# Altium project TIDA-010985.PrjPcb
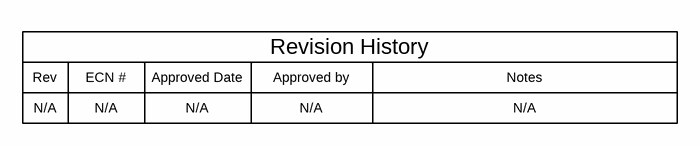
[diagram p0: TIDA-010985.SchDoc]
TID: N/A; TechSupport: http://www.ti.com/support; SCH_Rev: E2; PRJ_Title: Insulation Monitor; PRJ_Number: TIDA-010985; PRJ_Engineer: Kelvin Le; PRJ_Customer: Public Release; PCB_Rev: E2; PCB_Layout: Kelvin Le; CopyrightYear: 2025
5 sheets, 150 parts. Net scope: global (net labels, ports and power ports of the same name join across sheets).
Board file: TIDA-010985.PcbDoc
Sheets:
  TIDA-010985.SchDoc
  TIDA-010985_AFE.SchDoc
  TIDA-010985_Hardware.SchDoc
  TIDA-010985_Connectors_Aux_PWR.SchDoc
  TIDA-010985_CAN.SchDoc

## Sheet TIDA-010985.SchDoc
size 431 x 279 mm; Date: Not shown in title block; ApprovedBy: Not shown in title block; CheckedBy: Not shown in title block; Author: Not shown in title block; CompanyName: Not shown in title block; Engineer: Not shown in title block; Organization: Not shown in title block; Address1: Not shown in title block; Address2: Not shown in title block; Address3: Not shown in title block; Address4: Not shown in title block; DocumentNumber: 1; Revision: Use project parameter SCH_Rev; SheetNumber: 1; SheetTotal: 5; PageSetup: Record=PageOptions¦CenterHorizontal=True¦CenterVertical=True¦PrintScale=1.00¦XCorrection=1.00¦YCorrection=1.00¦PrintKind=0¦BorderSize=5000000¦LeftOffset=0¦BottomOffset=0¦Orientation=2¦PaperLength=1000¦PaperWidth=1000¦Scale=100¦PaperSource=15¦PrintQuality=600¦MediaType=1¦DitherType=10¦PaperKind=Letter¦PrintScaleMode=1

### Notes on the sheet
- Rev
- N/A
- ECN #
- Approved Date
- Approved by
- Revision History
- Notes

## Sheet TIDA-010985_AFE.SchDoc
size 431 x 279 mm; Date: Not shown in title block; ApprovedBy: Not shown in title block; CheckedBy: Not shown in title block; Author: Not shown in title block; CompanyName: Not shown in title block; Engineer: Not shown in title block; Organization: Not shown in title block; Address1: Not shown in title block; Address2: Not shown in title block; Address3: Not shown in title block; Address4: Not shown in title block; DocumentNumber: 2; Revision: Use project parameter SCH_Rev; SheetNumber: 2; SheetTotal: 5; PageSetup: Record=PageOptions¦CenterHorizontal=True¦CenterVertical=True¦PrintScale=1.00¦XCorrection=1.00¦YCorrection=1.00¦PrintKind=0¦BorderSize=5000000¦LeftOffset=0¦BottomOffset=0¦Orientation=2¦PaperLength=1000¦PaperWidth=1000¦Scale=100¦PaperSource=15¦PrintQuality=600¦MediaType=1¦DitherType=10¦PaperKind=Letter¦PrintScaleMode=1
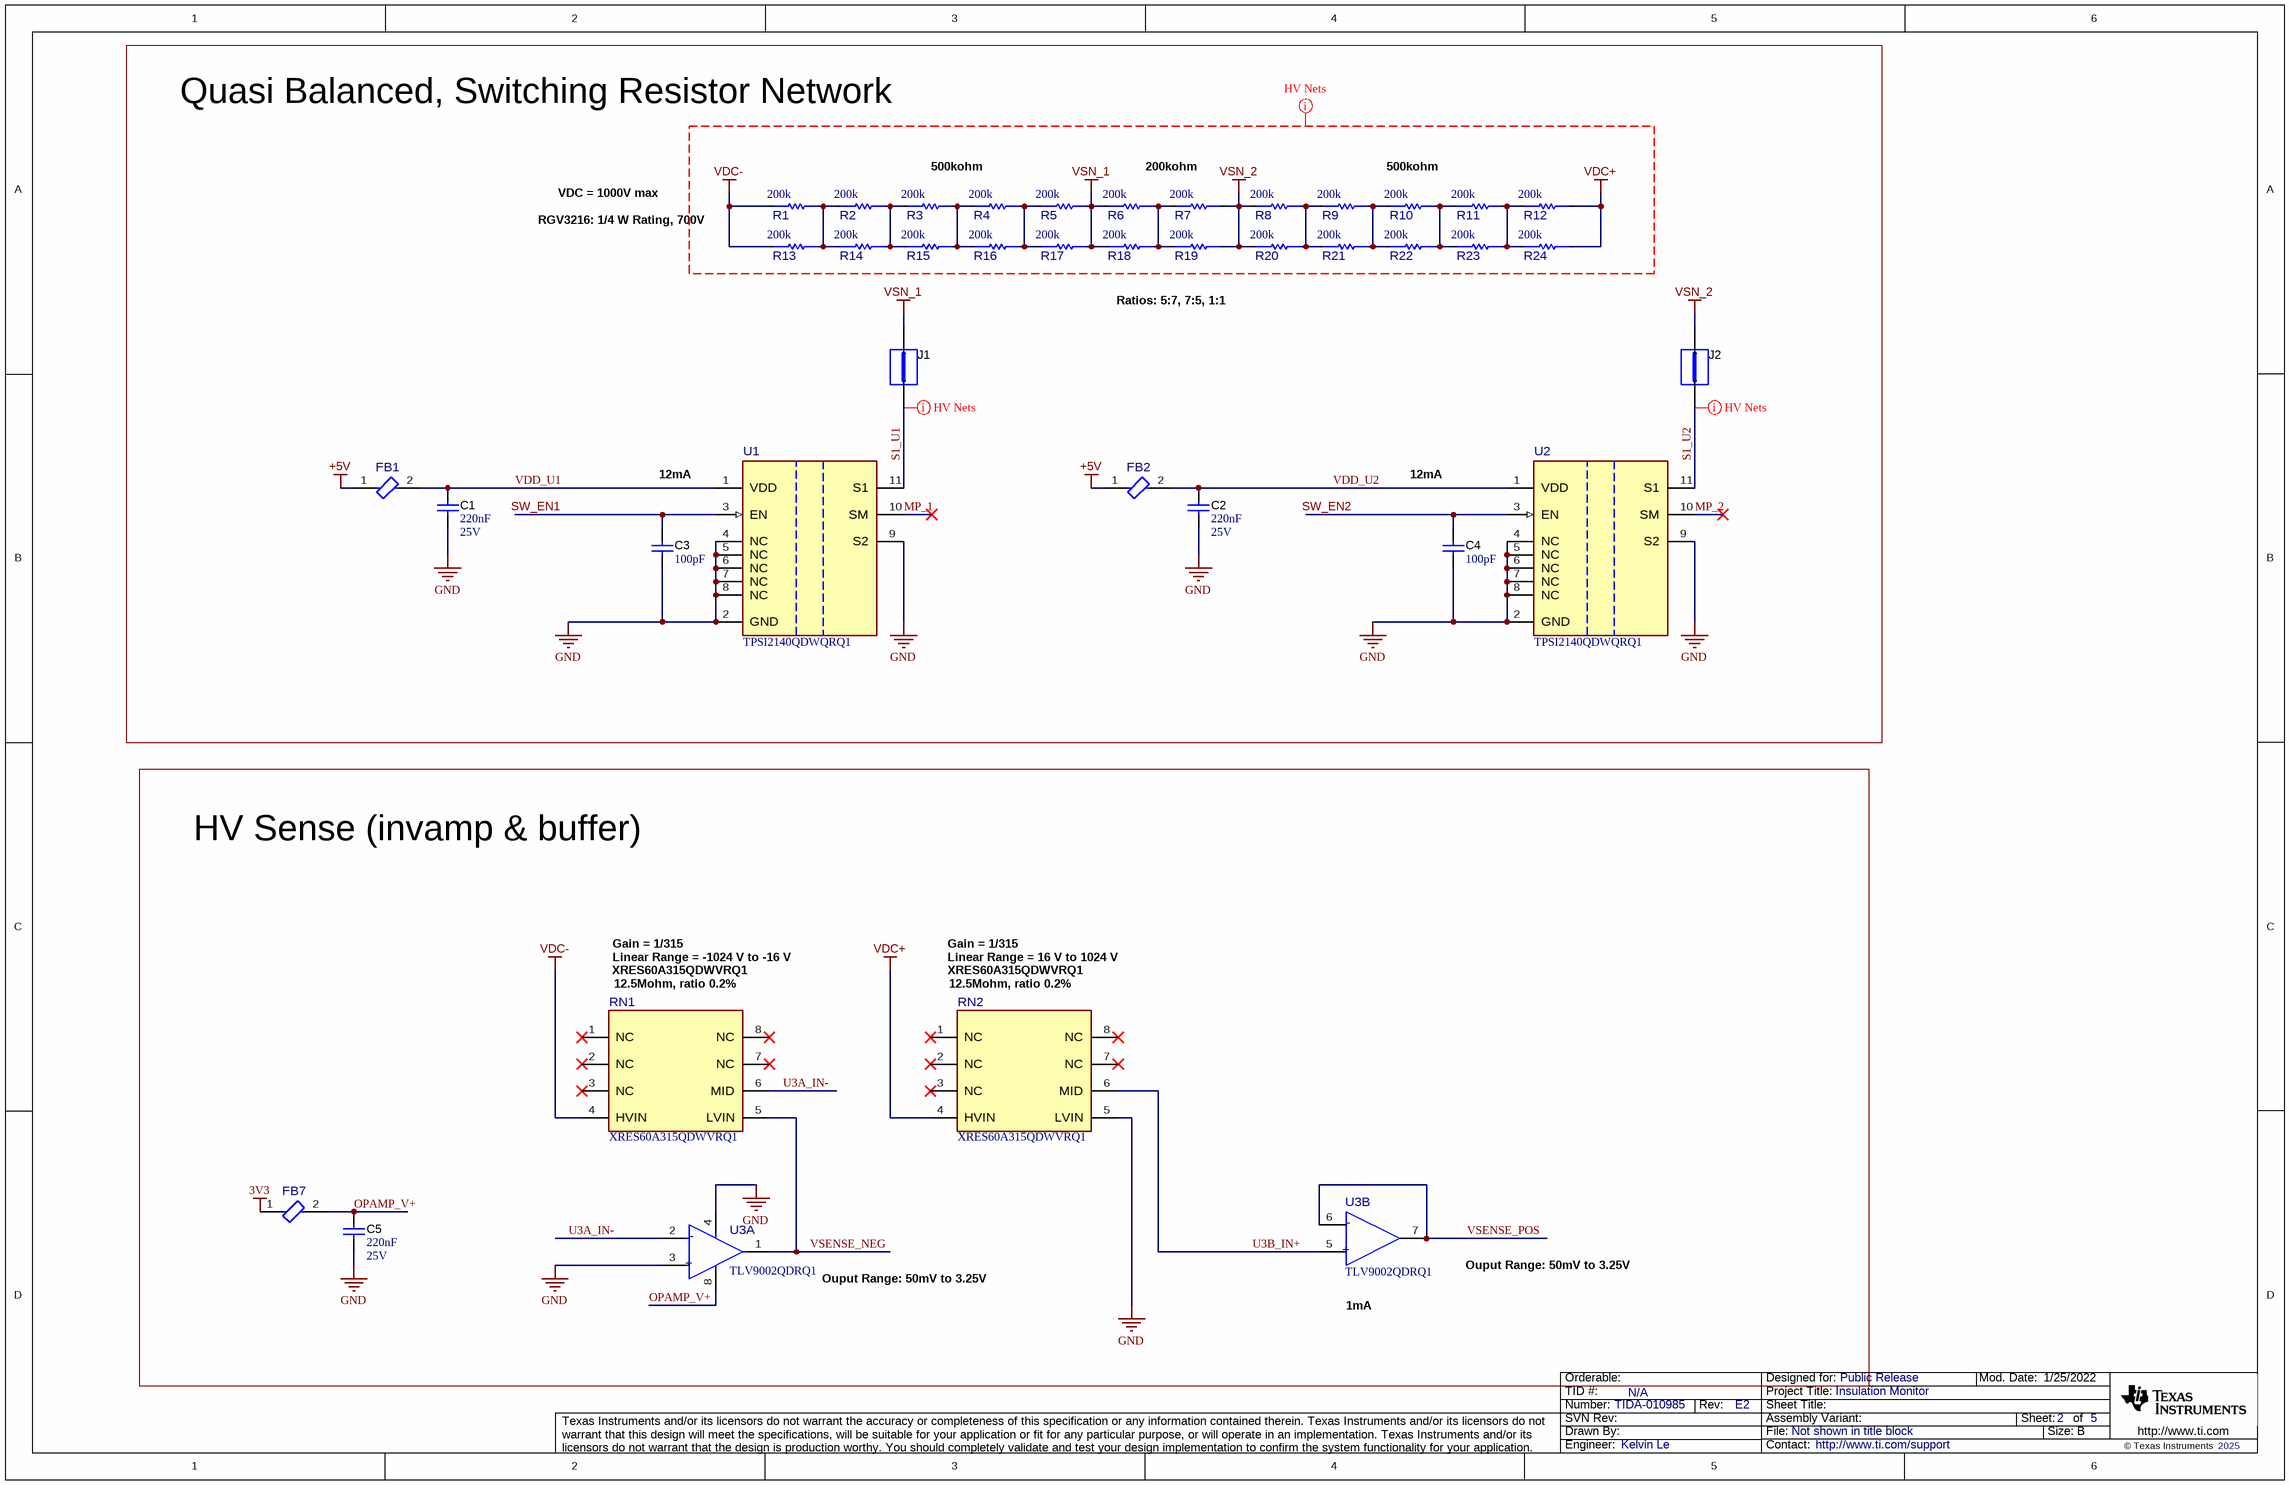
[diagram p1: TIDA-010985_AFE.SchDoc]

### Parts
C1  Cap_F: 220nF  VDC_V: 25V  [0603L]  (hidden comment: C0603C224J3RAC7867)
C2  Cap_F: 220nF  VDC_V: 25V  [0603L]  (hidden comment: C0603C224J3RAC7867)
C3  ValueDisplayed: 100pF  [0402L]  (hidden comment: GRM1555C1H101JA01D)
C4  ValueDisplayed: 100pF  [0402L]  (hidden comment: GRM1555C1H101JA01D)
C5  Cap_F: 220nF  VDC_V: 25V  [0603L]  (hidden comment: C0603C224J3RAC7867)
FB1  74269244182  [FP-74269244182_0402-MFG]  (value not drawn)
FB2  74269244182  [FP-74269244182_0402-MFG]  (value not drawn)
FB7  74269244182  [FP-74269244182_0402-MFG]  (value not drawn)
J1  999-11-113-10-000000  [Mill-Max_999-11-113-10-000000]  (value not drawn)
J2  999-11-113-10-000000  [Mill-Max_999-11-113-10-000000]  (value not drawn)
R1  value 200k  [FP-RGV3216P-2003-B-T1_1206-MFG]  (hidden comment: RGV3216P-2003-B-T1)
R2  value 200k  [FP-RGV3216P-2003-B-T1_1206-MFG]  (hidden comment: RGV3216P-2003-B-T1)
R3  value 200k  [FP-RGV3216P-2003-B-T1_1206-MFG]  (hidden comment: RGV3216P-2003-B-T1)
R4  value 200k  [FP-RGV3216P-2003-B-T1_1206-MFG]  (hidden comment: RGV3216P-2003-B-T1)
R5  value 200k  [FP-RGV3216P-2003-B-T1_1206-MFG]  (hidden comment: RGV3216P-2003-B-T1)
R6  value 200k  [FP-RGV3216P-2003-B-T1_1206-MFG]  (hidden comment: RGV3216P-2003-B-T1)
R7  value 200k  [FP-RGV3216P-2003-B-T1_1206-MFG]  (hidden comment: RGV3216P-2003-B-T1)
R8  value 200k  [FP-RGV3216P-2003-B-T1_1206-MFG]  (hidden comment: RGV3216P-2003-B-T1)
R9  value 200k  [FP-RGV3216P-2003-B-T1_1206-MFG]  (hidden comment: RGV3216P-2003-B-T1)
R10  value 200k  [FP-RGV3216P-2003-B-T1_1206-MFG]  (hidden comment: RGV3216P-2003-B-T1)
R11  value 200k  [FP-RGV3216P-2003-B-T1_1206-MFG]  (hidden comment: RGV3216P-2003-B-T1)
R12  value 200k  [FP-RGV3216P-2003-B-T1_1206-MFG]  (hidden comment: RGV3216P-2003-B-T1)
R13  value 200k  [FP-RGV3216P-2003-B-T1_1206-MFG]  (hidden comment: RGV3216P-2003-B-T1)
R14  value 200k  [FP-RGV3216P-2003-B-T1_1206-MFG]  (hidden comment: RGV3216P-2003-B-T1)
R15  value 200k  [FP-RGV3216P-2003-B-T1_1206-MFG]  (hidden comment: RGV3216P-2003-B-T1)
R16  value 200k  [FP-RGV3216P-2003-B-T1_1206-MFG]  (hidden comment: RGV3216P-2003-B-T1)
R17  value 200k  [FP-RGV3216P-2003-B-T1_1206-MFG]  (hidden comment: RGV3216P-2003-B-T1)
R18  value 200k  [FP-RGV3216P-2003-B-T1_1206-MFG]  (hidden comment: RGV3216P-2003-B-T1)
R19  value 200k  [FP-RGV3216P-2003-B-T1_1206-MFG]  (hidden comment: RGV3216P-2003-B-T1)
R20  value 200k  [FP-RGV3216P-2003-B-T1_1206-MFG]  (hidden comment: RGV3216P-2003-B-T1)
R21  value 200k  [FP-RGV3216P-2003-B-T1_1206-MFG]  (hidden comment: RGV3216P-2003-B-T1)
R22  value 200k  [FP-RGV3216P-2003-B-T1_1206-MFG]  (hidden comment: RGV3216P-2003-B-T1)
R23  value 200k  [FP-RGV3216P-2003-B-T1_1206-MFG]  (hidden comment: RGV3216P-2003-B-T1)
R24  value 200k  [FP-RGV3216P-2003-B-T1_1206-MFG]  (hidden comment: RGV3216P-2003-B-T1)
RN1  XRES60A315QDWVRQ1  [DWV0008A-MFG]
RN2  XRES60A315QDWVRQ1  [DWV0008A-MFG]
U1  TPSI2140QDWQRQ1  [DWQ0011A-MFG]
U2  TPSI2140QDWQRQ1  [DWQ0011A-MFG]
U3  TLV9002QDRQ1  [D0008A-MFG]  (parts A,B of 2)

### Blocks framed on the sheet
Quasi Balanced, Switching Resistor Network: C1-C4 FB1 FB2 J1 J2 R1-R24 U1 U2
HV Sense (invamp & buffer): C5 FB7 RN1 RN2 U3

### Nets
3V3: FB7.1
+5V: FB1.1 FB2.1
GND: C1.2 C2.2 C3.2 C4.2 C5.2 RN2.5(LVIN) U1.2(GND) U1.4(NC) U1.5(NC) U1.6(NC) U1.7(NC) U1.8(NC) U1.9(S2) U2.2(GND) U2.4(NC) U2.5(NC) U2.6(NC) U2.7(NC) U2.8(NC) U2.9(S2) U3.3(IN1+) U3.4(V-)
VDC+: R12.2 R24.2 RN2.4(HVIN)
VDC-: R1.1 R13.1 RN1.4(HVIN)
VSN_1: J1.2 R5.2 R6.1 R17.2 R18.1
VSN_2: J2.2 R7.2 R8.1 R19.2 R20.1
MP_1: U1.10(SM)
MP_2: U2.10(SM)
OPAMP_V+: C5.1 FB7.2 U3.8(V+)
S1_U1: J1.1 U1.11(S1)
S1_U2: J2.1 U2.11(S1)
SW_EN1: C3.1 U1.3(EN)
SW_EN2: C4.1 U2.3(EN)
U3A_IN-: RN1.6(MID) U3.2(IN1-)
U3B_IN+: RN2.6(MID) U3.5(IN2+)
VDD_U1: C1.1 FB1.2 U1.1(VDD)
VDD_U2: C2.1 FB2.2 U2.1(VDD)
VSENSE_NEG: RN1.5(LVIN) U3.1(OUT1)
VSENSE_POS: U3.6(IN2-) U3.7(OUT2)
NetR1_2: R1.2 R2.1 R13.2 R14.1
NetR2_2: R2.2 R3.1 R14.2 R15.1
NetR3_2: R3.2 R4.1 R15.2 R16.1
NetR4_2: R4.2 R5.1 R16.2 R17.1
NetR6_2: R6.2 R7.1 R18.2 R19.1
NetR8_2: R8.2 R9.1 R20.2 R21.1
NetR9_2: R9.2 R10.1 R21.2 R22.1
NetR10_2: R10.2 R11.1 R22.2 R23.1
NetR11_2: R11.2 R12.1 R23.2 R24.1

Not connected (* = marked no-connect by the designer): RN1 1(NC)* 2(NC)* 3(NC)* 7(NC)* 8(NC)*; RN2 1(NC)* 2(NC)* 3(NC)* 7(NC)* 8(NC)*

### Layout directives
net class HV_Nets: S1_U1, S1_U2, VDC+, VDC-, VSN_1, VSN_2

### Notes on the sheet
- 500kohm
- 200kohm
- VDC = 1000V max
- RGV3216: 1/4 W Rating, 700V
- Ratios: 5:7, 7:5, 1:1
- 12mA
- Gain = 1/315
- XRES60A315QDWVRQ1
- Linear Range = -1024 V to -16 V
- Linear Range = 16 V to 1024 V
- (near RN1) 12.5Mohm, ratio 0.2%
- (near RN2) 12.5Mohm, ratio 0.2%
- Ouput Range: 50mV to 3.25V
- (near U3) 1mA

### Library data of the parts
C1 C2 C5 = CMP-0006902-5: CAP, CERM, 0.22 uF, 25 V, +/- 5%, X7R, 0603; Manufacturer: Kemet; TaMin_C: -55°C; Polarized: N; SizeAreaWB_mm2: 4.68; Value1: Unknown; U/M: EA; Value: 0.22uF; TaMax_C: 125°C; SizeZ_mm: 1; SizeX_mm: 1.6; SizeY_mm: 0.8; Cap_Case: 0603; SizeArea_mm2: 1.28; AEC Category: Q200
C3 C4 = CMP-0006410-2: CAP, CERM, 100 pF, 50 V, +/- 5%, C0G/NP0, 0402; Manufacturer: MuRata; TaMin_C: -55°C; Polarized: N; SizeAreaWB_mm2: 3; Value1: Unknown; U/M: EA; Value: 100pF; TaMax_C: 125°C; SizeZ_mm: 0.6; SizeX_mm: 1; SizeY_mm: 0.5; Cap_Case: 0402; Value2: 50V; AEC Category: Q200
FB1 FB2 FB7 = CMP-0091663-1: 1.8 kOhms @ 100MHz 1 Power, Signal Line Ferrite Bead 0402 (1005 Metric) 210mA 2.1Ohm; Manufacturer: Wurth Electronics; SizeZ_mm: 0.55mm; AEC Qualified: No; DCR_ohm: 2.1; Tolerance_%: 25%; Test Frequency: 1GHz; Impedance At Frequency: 1800Ω @ 100MHz
J1 J2 = CMP-0055045-1: Shorting Jumper, 7.62mm, 2 Position, Gold, TH; Manufacturer: Mill-Max; CNHeader: FALSE; Gender: Male; Pitch_mm: 7.62; Cert_UL: Y
R1-R24 = CMP-0126488-1: 200 kOhms ±0.1% 0.25W, 1/4W Chip Resistor 1206 (3216 Metric) Anti-Sulfur, Automotive AEC-Q200, High Voltage Thin Film; Manufacturer: Susumu; AEC Grade: Grade 0; AEC Qualified: Yes; Power_W: 250mW; SizeZ_mm: 0.55mm; TempCo: 25ppm/°C; VDC_V: 700V
RN1 RN2 = CMP-0126545-1: Manufacturer: Texas Instruments; SizeZ_mm: 2.8mm; AEC Qualified: Yes; AEC Grade: Grade 1; Standoff Height: 0.36mm
U1 U2 = CMP-0090961-3: Isolated Solid State Relay; Manufacturer: Texas Instruments; CompType: IC; Output Voltage: 1400V; On State Resistance: 85Ω; Standoff Height: 0.1mm; TaMax_C: +125°C; Voltage_Isolation_Vrms: 1414VDC; AEC Grade: Grade 1; AEC Qualified: Yes; SizeZ_mm: 2.65mm; TJmax_C: +150°C; TaMin_C: -40°C; Contact Form: SPST; AEC Category: Q200
U3 = CMP-0126497-1: Automotive-grade, dual, 5.5-V, 1-MHz, RRIO operational amplifier for cost-optimized applications 8-SOIC -40 to 125; Manufacturer: Texas Instruments; SizeZ_mm: 1.75mm; AEC Qualified: Yes; AEC Grade: Grade 1; Gain Bandwidth: 1MHz; Input Bias Current: 5pA; Input Offset Voltage: 0.4mV; Max Dual Supply Voltage: 2.75V; Max Supply Voltage: 5.5V; Min Dual Supply Voltage: 900mV; Min Supply Voltage: 1.8V; Nominal Supply Current: 60uA; Number Of Channels: 2; Output Current Per Channel: 40mA; Response Time: 3us; Standoff Height: 0.11mm; TaMax_C: +125°C; TaMin_C: -40°C; TJmax_C: +150°C; Voltage Gain: 130dB

## Sheet TIDA-010985_Hardware.SchDoc
size 431 x 279 mm; Date: Not shown in title block; ApprovedBy: Not shown in title block; CheckedBy: Not shown in title block; Author: Not shown in title block; CompanyName: Not shown in title block; Engineer: Not shown in title block; Organization: Not shown in title block; Address1: Not shown in title block; Address2: Not shown in title block; Address3: Not shown in title block; Address4: Not shown in title block; DocumentNumber: 5; Revision: Use project parameter SCH_Rev; SheetNumber: 5; SheetTotal: 5; PageSetup: Record=PageOptions¦CenterHorizontal=True¦CenterVertical=True¦PrintScale=1.00¦XCorrection=1.00¦YCorrection=1.00¦PrintKind=0¦BorderSize=5000000¦LeftOffset=0¦BottomOffset=0¦Orientation=2¦PaperLength=1000¦PaperWidth=1000¦Scale=100¦PaperSource=15¦PrintQuality=600¦MediaType=1¦DitherType=10¦PaperKind=Letter¦PrintScaleMode=1
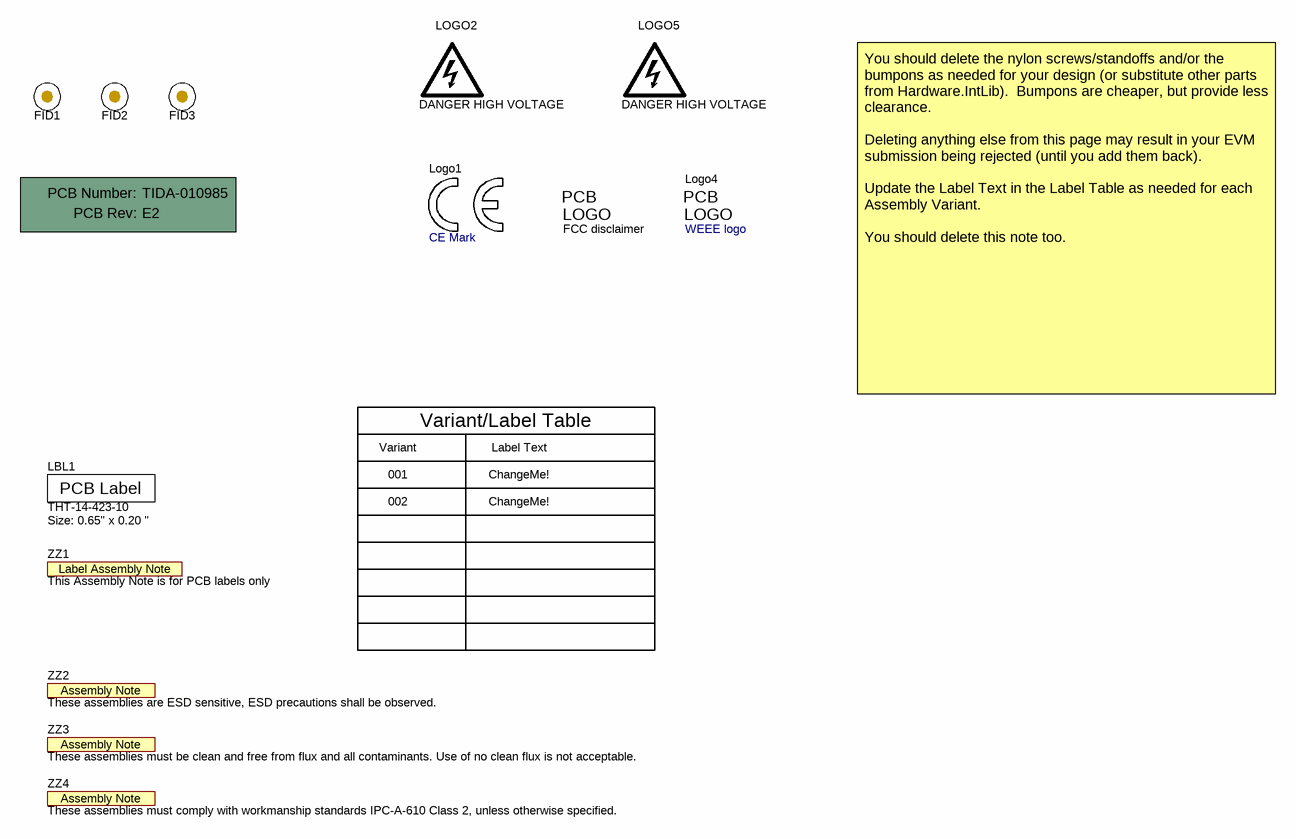
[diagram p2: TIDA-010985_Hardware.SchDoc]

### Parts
!PCB1  Printed Circuit Board  (value not drawn)  (mechanical)
FID1  Fiducial  [Fiducial10-20]  (value not drawn)
FID2  Fiducial  [Fiducial10-20]  (value not drawn)
FID3  Fiducial  [Fiducial10-20]  (value not drawn)
LBL1  THT-14-423-10  Note: Size: 0.65" x 0.20 "  [Label_650x200]
Logo1  CE Mark  [CE_Mark_5mm]  (no BOM)
LOGO2  DANGER HIGH VOLTAGE  [IEC_HighVoltage_Small]  (no BOM)
Logo3  FCC disclaimer  [FCC_disclaimer]  (no BOM)
Logo4  WEEE logo  [WEEE_Minimum]  (no BOM)
LOGO5  DANGER HIGH VOLTAGE  [IEC_HighVoltage_Small]  (no BOM)
ZZ1  This Assembly Note is for PCB labels only  [AssemblyNoteLabel]  (no BOM)
ZZ2  These assemblies are ESD sensitive, ESD precautions shall be observed.  [AssemblyNote]  (no BOM)
ZZ3  These assemblies must be clean and free from flux and all contaminants. Use of no clean flux is not acceptable.  [AssemblyNote]  (no BOM)
ZZ4  These assemblies must comply with workmanship standards IPC-A-610 Class 2, unless otherwise specified.  [AssemblyNote]  (no BOM)

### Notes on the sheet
- Variant
- Variant/Label Table
- Label Text
- You should delete the nylon screws/standoffs and/or the bumpons as needed for your design (or substitute other parts from Hardware.IntLib).  Bumpons are cheaper, but provide less clearance.
  Deleting anything else from this page may result in your EVM submission being rejected (until you add them back).
  Update the Label Text in the Label Table as needed for each Assembly Variant.
  You should delete this note too.
- 001
- 002
- ChangeMe!

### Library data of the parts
!PCB1 = CMP-0003618-2: Manufacturer: Any; PartNumber: TIDA-010985
FID1-FID3 = CMP-0077181-1: Fiducial mark.  There is nothing to buy or mount.
LBL1 = CMP-0003625-1: Thermal Transfer Printable Labels, 0.650" W x 0.200" H - 10,000 per roll; Manufacturer: Brady; CompType: Label
Logo1 = CMP-0074844-2: Manufacturer: Texas Instruments; SymbolCreator: a0412235; AEC Category: Q200; CompType: IC
LOGO2 LOGO5 = CMP-0074835-1: IEC 61010-1 High Voltage Warning; Library Reference: IEC_HighVoltage; SymbolCreator: a0412235
Logo3 = CMP-0074847-1: FCC_disclaimer; Library Reference: Logo
Logo4 = CMP-0074769-4: Manufacturer: Texas Instruments; CompType: IC; AEC Category: Q200
ZZ1 = CMP-0003616-3
ZZ2 = CMP-0077236-1
ZZ3 = CMP-0077237-1
ZZ4 = CMP-0077238-1

## Sheet TIDA-010985_Connectors_Aux_PWR.SchDoc
size 431 x 279 mm; DocumentNumber: 3; SheetNumber: 3; SheetTotal: 5; PageSetup: Record=PageOptions¦CenterHorizontal=True¦CenterVertical=True¦PrintScale=1.00¦XCorrection=1.00¦YCorrection=1.00¦PrintKind=0¦BorderSize=5000000¦LeftOffset=0¦BottomOffset=0¦Orientation=2¦PaperLength=1000¦PaperWidth=1000¦Scale=100¦PaperSource=15¦PrintQuality=600¦MediaType=1¦DitherType=10¦PaperKind=Letter¦PrintScaleMode=1
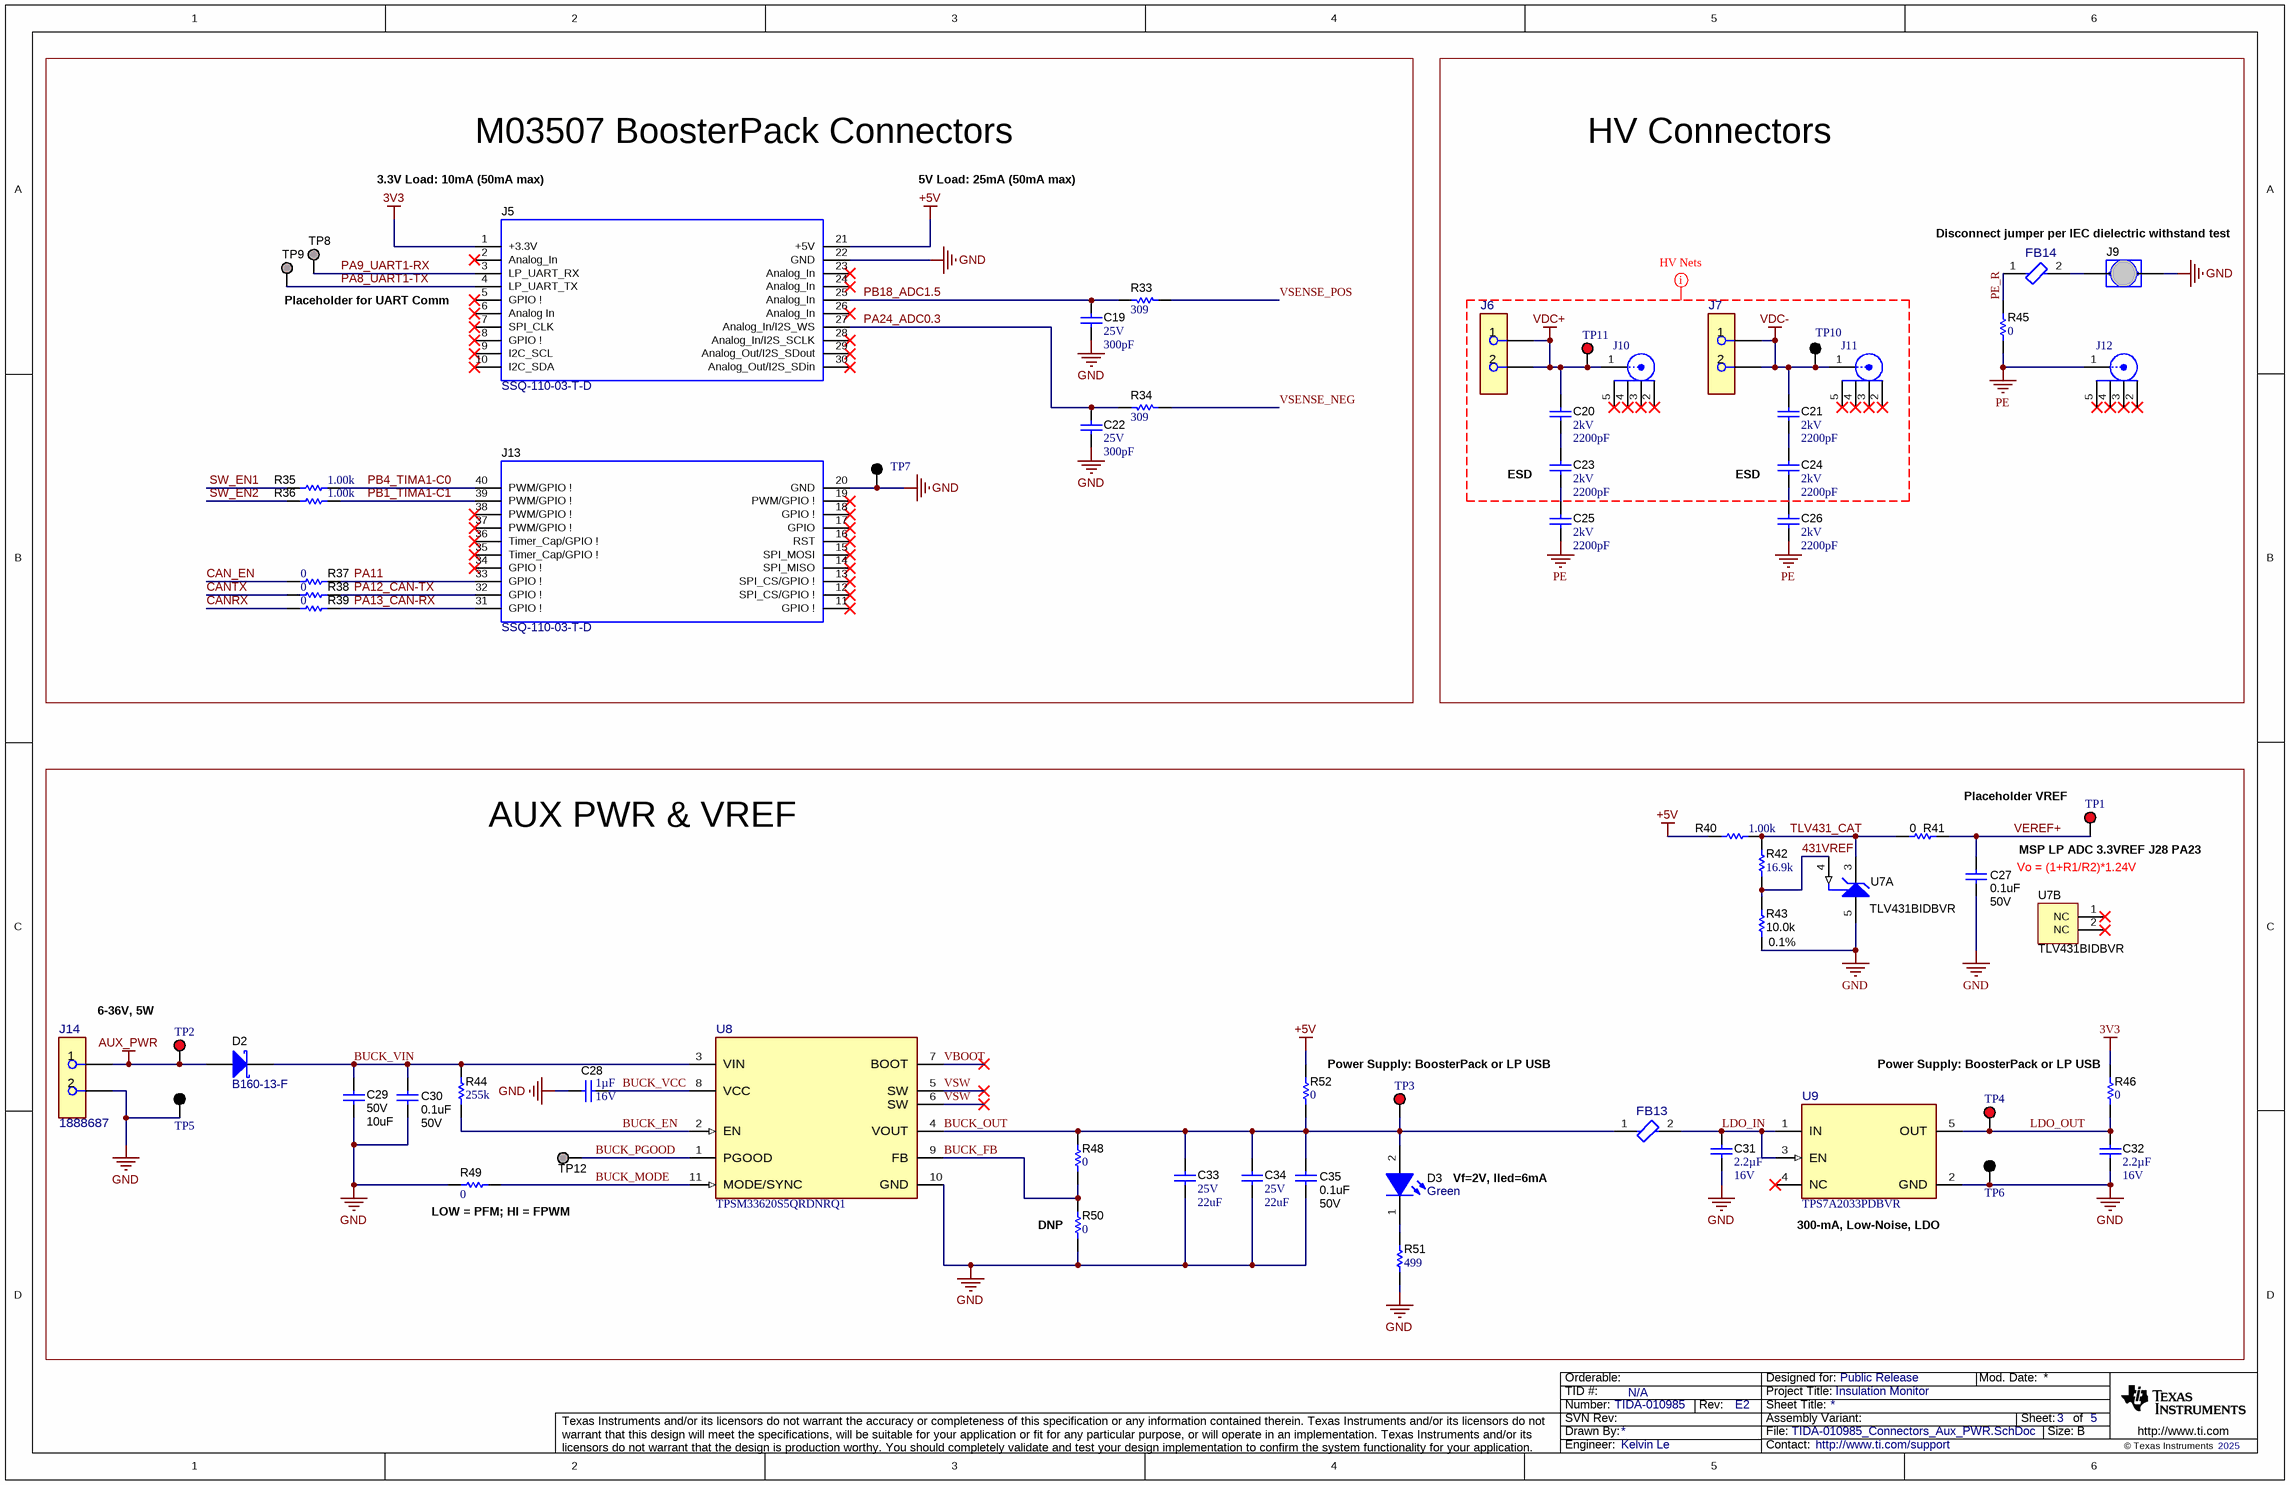
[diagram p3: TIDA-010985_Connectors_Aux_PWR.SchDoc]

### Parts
C19  VDC_V: 25V  ValueDisplayed: 300pF  [0402L]  (hidden comment: GRM1555C1E301JA01D)
C20  VDC_V: 2kV  ValueDisplayed: 2200pF  [1206_180]  (hidden comment: 1206J2K00222KXR)
C21  VDC_V: 2kV  ValueDisplayed: 2200pF  [1206_180]  (hidden comment: 1206J2K00222KXR)
C22  VDC_V: 25V  ValueDisplayed: 300pF  [0402L]  (hidden comment: GRM1555C1E301JA01D)
C23  VDC_V: 2kV  ValueDisplayed: 2200pF  [1206_180]  (hidden comment: 1206J2K00222KXR)
C24  VDC_V: 2kV  ValueDisplayed: 2200pF  [1206_180]  (hidden comment: 1206J2K00222KXR)
C25  VDC_V: 2kV  ValueDisplayed: 2200pF  [1206_180]  (hidden comment: 1206J2K00222KXR)
C26  VDC_V: 2kV  ValueDisplayed: 2200pF  [1206_180]  (hidden comment: 1206J2K00222KXR)
C27  VDC_V: 50V  ValueDisplayed: 0.1uF  [0402L]  (hidden comment: GCM155R71H104KE02D)
C28  Cap_F: 1µF  VDC_V: 16V  [0603L]  (hidden comment: GCM188R71C105KA64D)
C29  VDC_V: 50V  ValueDisplayed: 10uF  [1206_180L]  (hidden comment: CL31B106KBHNNNE)
C30  VDC_V: 50V  ValueDisplayed: 0.1uF  [0402L]  (hidden comment: GCM155R71H104KE02D)
C31  Cap_F: 2.2µF  VDC_V: 16V  [0603L]  (hidden comment: EMK107BB7225KA-T)
C32  Cap_F: 2.2µF  VDC_V: 16V  [0603L]  (hidden comment: EMK107BB7225KA-T)
C33  VDC_V: 25V  ValueDisplayed: 22uF  [1210_270L]  (hidden comment: GRM32ER71E226KE15L)
C34  VDC_V: 25V  ValueDisplayed: 22uF  [1210_270L]  (hidden comment: GRM32ER71E226KE15L)
C35  VDC_V: 50V  ValueDisplayed: 0.1uF  [0402L]  (hidden comment: GCM155R71H104KE02D)
D2  B160-13-F  [SMA]
D3  value Green  [WL-SMCW_GREEN]  (hidden comment: 150060VS75000)
FB13  74269244182  [FP-74269244182_0402-MFG]  (value not drawn)
FB14  BLM18KG102SH1D  [FP-BLM18KG102SH1D_0603-MFG]  (value not drawn)
J5  SSQ-110-03-T-D  [BoosterPack_40pin_J1J3]
J6  1888687  [FP-1888687_HDR2-MFG]  (value not drawn)
J7  1888687  [FP-1888687_HDR2-MFG]  (value not drawn)
J9  999-11-113-10-000000  [Mill-Max_999-11-113-10-000000]  (value not drawn)
J10  FCR7350R  [Cliff_FCR7350R]  (value not drawn)
J11  FCR7350B  [Cliff_FCR7350B]  (value not drawn)
J12  FCR7350G  [FP-FCR7350G_CONN_BANANA_JACK-MFG]  (value not drawn)
J13  SSQ-110-03-T-D  [BoosterPack_40pin_J2J4]
J14  1888687  [FP-1888687_HDR2-MFG]
R33  ValueDisplayed: 309  [0402L]  (hidden comment: CRCW0402309RFKED)
R34  ValueDisplayed: 309  [0402L]  (hidden comment: CRCW0402309RFKED)
R35  ValueDisplayed: 1.00k  [0603]  (hidden comment: RC0603FR-071KL)
R36  ValueDisplayed: 1.00k  [0603]  (hidden comment: RC0603FR-071KL)
R37  ValueDisplayed: 0  [0603]  (hidden comment: RC0603JR-070RL)
R38  ValueDisplayed: 0  [0603]  (hidden comment: RC0603JR-070RL)
R39  ValueDisplayed: 0  [0603]  (hidden comment: RC0603JR-070RL)
R40  ValueDisplayed: 1.00k  [0603L]  (hidden comment: RC0603FR-071KL)
R41  value 0  [0603L]  (hidden comment: Resistor)
R42  ValueDisplayed: 16.9k  [0603L]  (hidden comment: RT0603BRD0716K9L)
R43  Value1: 0.1%  ValueDisplayed: 10.0k  [0603L]  (hidden comment: RG1608P-103-B-T5)
R44  ValueDisplayed: 255k  [0402L]  (hidden comment: CRCW0402255KFKED)
R45  ValueDisplayed: 0  [0603]  (hidden comment: RC0603JR-070RL)
R46  ValueDisplayed: 0  [0603L]  (hidden comment: RC0603JR-070RL)
R48  ValueDisplayed: 0  [0402L]  (hidden comment: CRCW04020000Z0ED)
R49  ValueDisplayed: 0  [0402L]  (hidden comment: CRCW04020000Z0ED)
R50  ValueDisplayed: 0  [0402L]  (hidden comment: CRCW04020000Z0ED)
R51  ValueDisplayed: 499  [0603L]  (hidden comment: CRCW0603499RFKEAC)
R52  ValueDisplayed: 0  [0603L]  (hidden comment: RC0603JR-070RL)
TP1  5010  [Keystone5010]  (value not drawn)
TP2  5010  [Keystone5010]  (value not drawn)
TP3  5010  [Keystone5010]  (value not drawn)
TP4  5010  [Keystone5010]  (value not drawn)
TP5  5011  [Keystone5011]  (value not drawn)
TP6  5011  [Keystone5011]  (value not drawn)
TP7  5011  [Keystone5011]  (value not drawn)
TP8  TP_SM_1MM  [TP_SM_1MM]  (value not drawn)  (no BOM)
TP9  TP_SM_1MM  [TP_SM_1MM]  (value not drawn)  (no BOM)
TP10  5011  [Keystone5011]  (value not drawn)
TP11  5010  [Keystone5010]  (value not drawn)
TP12  TP_SM_1MM  [TP_SM_1MM]  (value not drawn)  (no BOM)
U7  TLV431BIDBVR  [DBV0005A_N]  (parts A,B of 2)
U8  TPSM33620S5QRDNRQ1  [RDN0011A-MFG]
U9  TPS7A2033PDBVR  [DBV0005A-MFG]

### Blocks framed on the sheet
M03507 BoosterPack Connectors: C19 C22 J5 J13 R33-R39 TP7-TP9
HV Connectors: C20 C21 C23-C26 FB14 J6 J7 J9-J12 R45 TP10 TP11
AUX PWR & VREF: C27-C35 D2 D3 FB13 J14 R40-R44 R46 R48-R52 TP1-TP6 TP12 U7-U9

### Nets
3V3: J5.1(+3.3V) R46.2
+5V: J5.21(+5V) R40.1 R52.2
AUX_PWR: D2.2(A) J14.1 TP2.1
GND: C19.2 C22.2 C27.1 C28.1 C29.2 C30.1 C31.2 C32.2 C33.2 C34.2 C35.1 J5.22(GND) J9.2 J13.20(GND) J14.2 R43.1 R49.2 R50.1 R51.1 TP5.1 TP6.1 TP7.1 U7.5(ANODE) U8.10(GND) U9.2(GND)
PE: C25.2 C26.2 J12.1 R45.1
VDC+: C20.1 J6.1 J6.2 J10.1 TP11.1
VDC-: C21.1 J7.1 J7.2 J11.1 TP10.1
431VREF: R42.1 R43.2 U7.4(REF)
BUCK_EN: R44.1 U8.2(EN)
BUCK_FB: R48.1 R50.2 U8.9(FB)
BUCK_MODE: R49.1 U8.11(MODE/SYNC)
BUCK_OUT: C33.1 C34.1 C35.2 D3.2(A) FB13.1 R48.2 R52.1 TP3.1 U8.4(VOUT)
BUCK_PGOOD: TP12.1 U8.1(PGOOD)
BUCK_VCC: C28.2 U8.8(VCC)
BUCK_VIN: C29.1 C30.2 D2.1(K) R44.2 U8.3(VIN)
CAN_EN: R37.1
CANRX: R39.1
CANTX: R38.1
LDO_IN: C31.1 FB13.2 U9.1(IN) U9.3(EN)
LDO_OUT: C32.1 R46.1 TP4.1 U9.5(OUT)
PA8_UART1-TX: J5.4(LP_UART_TX) TP9.1
PA9_UART1-RX: J5.3(LP_UART_RX) TP8.1
PA11: J13.33(GPIO_!) R37.2
PA12_CAN-TX: J13.32(GPIO_!) R38.2
PA13_CAN-RX: J13.31(GPIO_!) R39.2
PA24_ADC0.3: C22.1 J5.27(Analog_In/I2S_WS) R34.2
PB1_TIMA1-C1: J13.39(PWM/GPIO_!) R36.2
PB4_TIMA1-C0: J13.40(PWM/GPIO_!) R35.2
PB18_ADC1.5: C19.1 J5.25(Analog_In) R33.2
PE_R: FB14.1 R45.2
SW_EN1: R35.1
SW_EN2: R36.1
TLV431_CAT: R40.2 R41.2 R42.2 U7.3(CATHODE)
VBOOT: U8.7(BOOT)
VEREF+: C27.2 R41.1 TP1.1
VSENSE_NEG: R34.1
VSENSE_POS: R33.1
VSW: U8.5(SW) U8.6(SW)
NetC20_2: C20.2 C23.1
NetC21_2: C21.2 C24.1
NetC23_2: C23.2 C25.1
NetC24_2: C24.2 C26.1
NetD3_1: D3.1(K) R51.2
NetFB14_2: FB14.2 J9.1

Not connected (* = marked no-connect by the designer): J5 2(Analog_In)* 5(GPIO_!)* 6(Analog_In)* 7(SPI_CLK)* 8(GPIO_!)* 9(I2C_SCL)* 10(I2C_SDA)* 23(Analog_In)* 24(Analog_In)* 26(Analog_In)* 28(Analog_In/I2S_SCLK)* 29(Analog_Out/I2S_SDout)* 30(Analog_Out/I2S_SDin)*; J10 2* 3* 4* 5*; J11 2* 3* 4* 5*; J12 2* 3* 4* 5*; J13 11(GPIO_!)* 12(SPI_CS/GPIO_!)* 13(SPI_CS/GPIO_!)* 14(SPI_MISO)* 15(SPI_MOSI)* 16(RST)* 17(GPIO)* 18(GPIO_!)* 19(PWM/GPIO_!)* 34(GPIO_!)* 35(Timer_Cap/GPIO_!)* 36(Timer_Cap/GPIO_!)* 37(PWM/GPIO_!)* 38(PWM/GPIO_!)*; U7 1(NC)* 2(NC)*; U9 4(NC)*

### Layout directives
net class HV_Nets: VDC+, VDC-

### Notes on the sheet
- 3.3V Load: 10mA (50mA max)
- 5V Load: 25mA (50mA max)
- Disconnect jumper per IEC dielectric withstand test
- Placeholder for UART Comm
- ESD
- Placeholder VREF
- Vo = (1+R1/R2)*1.24V
- (near TP1) MSP LP ADC 3.3VREF J28 PA23
- 6-36V, 5W
- Power Supply: BoosterPack or LP USB
- (near R46) Power Supply: BoosterPack or LP USB
- (near R49) LOW = PFM; HI = FPWM
- (near R50) DNP
- Vf=2V, Iled=6mA
- (near U9) 300-mA, Low-Noise, LDO

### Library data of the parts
C19 C22 = CMP-0006376-2: CAP, CERM, 300 pF, 25 V, +/- 5%, C0G/NP0, 0402; Manufacturer: MuRata; TaMin_C: -55°C; Polarized: N; SizeAreaWB_mm2: 3; Value1: Unknown; U/M: EA; Value: 300pF; TaMax_C: 125°C; SizeZ_mm: 0.6; SizeX_mm: 1; SizeY_mm: 0.5; Cap_Case: 0402; AEC Category: Q200
C20 C21 C23-C26 = CMP-0077201-1: CAP, CERM, 2200 pF, 2000 V,+/- 10%, X7R, AEC-Q200 Grade 1, 1206; Manufacturer: Knowles Capacitors; TaMin_C: -55°C; Polarized: N; SizeAreaWB_mm2: 10.92; U/M: EA; Value: 2200pF; TaMax_C: 125°C; SizeZ_mm: 1.8; SizeX_mm: 3.2; SizeY_mm: 1.6; Cap_Case: 1206; Value2: 2000V; SizeArea_mm2: 5.12; AEC Qualified: Y; Cap_F: 2.2nF; AEC Grade: 1; AEC Category: Q200
C27 C30 C35 = CMP-0006356-2: CAP, CERM, 0.1 uF, 50 V, +/- 10%, X7R, AEC-Q200 Grade 1, 0402; Manufacturer: MuRata; TaMin_C: -55°C; Polarized: N; SizeAreaWB_mm2: 3; Value1: Unknown; U/M: EA; Value: 0.1uF; TaMax_C: 125°C; SizeZ_mm: 0.6; SizeX_mm: 1; SizeY_mm: 0.5; Cap_Case: 0402; AEC Qualified: Y; Cap_F: 100nF; AEC Category: Q200
C28 = CMP-0007136-5: CAP, CERM, 1 uF, 16 V, +/- 10%, X7R, AEC-Q200 Grade 1, 0603; Manufacturer: MuRata; TaMin_C: -55°C; Polarized: N; SizeAreaWB_mm2: 4.68; Value1: Unknown; U/M: EA; Value: 1uF; TaMax_C: 125°C; SizeZ_mm: 1; SizeX_mm: 1.6; SizeY_mm: 0.8; Cap_Case: 0603; SizeArea_mm2: 1.28; AEC Qualified: Y; AEC Category: Q200
C29 = CMP-0008802-2: CAP, CERM, 10 uF, 50 V, +/- 10%, X7R, 1206; Manufacturer: Samsung; TaMin_C: -55°C; Polarized: N; SizeAreaWB_mm2: 10.92; Value1: Unknown; U/M: EA; Value: 10uF; TaMax_C: 125°C; SizeZ_mm: 1.8; SizeX_mm: 3.2; SizeY_mm: 1.6; Cap_Case: 1206; SizeArea_mm2: 5.12; Cap_F: 10µF; AEC Category: Q200
C31 C32 = CMP-0007121-4: CAP, CERM, 2.2 uF, 16 V, +/- 10%, X7R, 0603; Manufacturer: Taiyo Yuden; TaMin_C: -55°C; Polarized: N; SizeAreaWB_mm2: 4.68; Value1: Unknown; U/M: EA; Value: 2.2uF; TaMax_C: 125°C; SizeZ_mm: 1; SizeX_mm: 1.6; SizeY_mm: 0.8; Cap_Case: 0603; SizeArea_mm2: 1.28; AEC Category: Q200
C33 C34 = CMP-0009224-2: CAP, CERM, 22 uF, 25 V, +/- 10%, X7R, 1210; Manufacturer: MuRata; TaMin_C: -55°C; Polarized: N; SizeAreaWB_mm2: 14.7; Value1: Unknown; U/M: EA; Value: 22uF; TaMax_C: 125°C; SizeZ_mm: 2.7; SizeX_mm: 3.2; SizeY_mm: 2.5; Cap_Case: 1210; SizeArea_mm2: 8; Cap_F: 22µF; AEC Category: Q200
D2 = CMP-0028389-2: Diode, Schottky, 60 V, 1 A, SMA; Manufacturer: Diodes Inc.; Green_Lifecycle: Not Set; SizeAreaWB_mm2: 37.3428; Green_REACh: Incomplete; TJmax_C: 150°C; AEC Category: Q101; SizeZ_mm: 2.87; RJC_CperW: 20; Io_A: 1A; SizeArea_mm2: 16.3228; Vf_V: 700mV; Value2: 0.7V; SizeY_mm: 2.92; Vr_V: 60V; SizeX_mm: 5.59; Value: 60V
D3 = CMP-0002894-2: LED, Green, SMD; Manufacturer: Wurth Elektronik; Type: AlInGaP; Value2: 2V; Io_A: 20mA; Value1: W
FB13 = CMP-0091663-1: as FB1 on sheet TIDA-010985_AFE
FB14 = CMP-0089381-1: 1 kOhms @ 100MHz 1 Power Line Ferrite Bead 0603 (1608 Metric) 1A 200mOhm; Manufacturer: Murata; AEC Grade: Grade 1; Tolerance_%: 25%; AEC Qualified: Yes; Impedance At Frequency: 1kΩ @ 100MHz; DCR_ohm: 0.2; SizeZ_mm: 0.95mm
J5 = CMP-0003837-4: Receptacle, 2.54mm, 10x2, Tin, TH; Alternate PartNumber: CRD-081413-A-G; Manufacturer: Samtec; Alternate Manufacturer: Major League Electronics; Note: Booster Pack 40 pin J1 and J3; Green_Lifecycle: Active; Green_REACh: Incomplete
J6 J7 J14 = CMP-0087130-1: Manufacturer: Phoenix Contact; Voltage_V: 400V; Current_A: 16A; Row_Count: 1; ContactFinish: Tin
J9 = CMP-0055045-1: as J1 on sheet TIDA-010985_AFE
J10 = CMP-0055799-1: Panel Socket, 24A, R/A, Gold, TH; Manufacturer: Cliff Electronic Components; CNHeader: FALSE; Gender: Female; Voltage_V: 1kV
J11 = CMP-0055798-1: Panel Socket, 24A, R/A, Gold, TH; Manufacturer: Cliff Electronic Components; CNHeader: FALSE; Gender: Female; Voltage_V: 1kV
J12 = CMP-0098294-2: Banana Test Connector, Socket, PCB Mount, 24 A, 1 kV, Gold Plated Contacts, Green; Manufacturer: CLIFF Electronic Components; Current_A: 24A; Voltage_V: 1kV; AEC Qualified: No; Conn Orientation: Right Angle; SizeZ_mm: 11.6mm; Standoff Height: 0.7mm
J13 = CMP-0078266-4: Receptacle, 2.54mm, 10x2, Tin, TH; Alternate PartNumber: CRD-081413-A-G; Manufacturer: Samtec; Alternate Manufacturer: Major League Electronics; Note: Booster Pack 40 pin J2 and J4; Green_REACh: Incomplete; Green_Lifecycle: Active
R33 R34 = CMP-0026283-2: RES, 309, 1%, 0.063 W, AEC-Q200 Grade 0, 0402; Manufacturer: Vishay-Dale; Power_W: 63mW; TempCo: 100 ppm/C; Value_Code: 309R; Value: 309; EIA_Code: E96; SizeX_mm: 1; SizeY_mm: 0.5; SizeZ_mm: 0.6; Value2: 0.063W; AEC Qualified: Y; VDC_V: 50V; AEC Category: Q200; AEC Grade: 0
R35 R36 R40 = CMP-0022895-5: RES, 1.00 k, 1%, 0.1 W, 0603; Manufacturer: Yageo; Power_W: 100mW; TempCo: 100 ppm/C; Value_Code: 1k00; Value: 1.00k; EIA_Code: E96; Res_ohm: 1k; SizeX_mm: 1.6; SizeY_mm: 0.8; SizeZ_mm: 1; Value2: 0.1W; SizeArea_mm2: 1.28; AEC Qualified: N; VDC_V: 75V; AEC Category: Q200; SizeAreaWB_mm2: 4.68
R37-R39 R45 R46 R52 = CMP-0025885-5: RES, 0, 5%, 0.1 W, 0603; Manufacturer: Yageo; Power_W: 100mW; TempCo: 200 ppm/C; Value_Code: 0000; Value: 0; EIA_Code: E24; SizeX_mm: 1.6; SizeZ_mm: 1; Value2: 0.1W; SizeArea_mm2: 1.28; AEC Qualified: N; VDC_V: 75V; AEC Category: Q200; SizeY_mm: 0.8; SizeAreaWB_mm2: 4.68
R41 = CMP-0025697-4: RES, 0, 5%, 0.1 W, AEC-Q200 Grade 0, 0603; PartNumber: CRCW06030000Z0EA; Manufacturer: Vishay-Dale; Value_Code: 0000; Power_W: 100mW; Value2: 0.1W; VDC_V: 75V; TempCo: 200 ppm/C; EIA_Code: E24; AEC Category: Q200; AEC Qualified: Y; SizeArea_mm2: 1.28; SizeX_mm: 1.6; SizeY_mm: 0.8; SizeZ_mm: 1
R42 = CMP-0023802-3: RES, 16.9 k, 0.1%, 0.1 W, 0603; Manufacturer: Yageo America; Power_W: 100mW; TempCo: 25 ppm/C; Value_Code: 16k9; U/M: EA; Value: 16.9k; EIA_Code: E192; SizeX_mm: 1.6; SizeY_mm: 0.8; SizeZ_mm: 1; Value2: 0.1W; SizeArea_mm2: 1.28; VDC_V: 75V; AEC Category: Q200
R43 = CMP-0023404-3: RES, 10.0 k, 0.1%, 0.1 W, 0603; Manufacturer: Susumu Co Ltd; Power_W: 100mW; TempCo: 25 ppm/C; Value_Code: 10k0; U/M: EA; Value: 10.0k; EIA_Code: E192; Res_ohm: 10k; SizeX_mm: 1.6; SizeY_mm: 0.8; SizeZ_mm: 1; Value2: 0.1W; SizeArea_mm2: 1.28; CompType: Resistor; VDC_V: 75V; AEC Category: Q200
R44 = CMP-0026199-2: RES, 255 k, 1%, 0.063 W, AEC-Q200 Grade 0, 0402; Manufacturer: Vishay-Dale; Power_W: 63mW; TempCo: 100 ppm/C; Value: 255k; EIA_Code: E96; SizeX_mm: 1; SizeY_mm: 0.5; SizeZ_mm: 0.6; Value2: 0.063W; AEC Qualified: Y; VDC_V: 50V; AEC Category: Q200; AEC Grade: 0
R48-R50 = CMP-0026822-3: RES, 0, 5%, 0.063 W, AEC-Q200 Grade 0, 0402; Manufacturer: Vishay-Dale; Power_W: 63mW; TempCo: 200 ppm/C; Value_Code: 0000; Value: 0; EIA_Code: E24; SizeX_mm: 1; SizeY_mm: 0.5; SizeZ_mm: 0.6; Value2: 0.063W; AEC Qualified: Y; VDC_V: 50V; AEC Category: Q200
R51 = CMP-0082532-1: RES, 499, 1%, 0.1 W, 0603; Manufacturer: Vishay-Dale; Power_W: 100mW; TempCo: 100 ppm/C; SizeAreaWB_mm2: 4.68; Value_Code: 499R; Value: 499; EIA_Code: E96; SizeX_mm: 1.6; SizeY_mm: 0.8; SizeZ_mm: 1; Value2: 0.1W; SizeArea_mm2: 1.28; AEC Qualified: N; VDC_V: 75V; AEC Category: Q200
TP1-TP4 TP11 = CMP-0055147-2: Test Point, Multipurpose, Red, TH; Manufacturer: Keystone Electronics; CT: TRUE; ContactFinish: Silver; Green_Lifecycle: Active; CNHeader: FALSE; Green_REACh: Passed
TP5-TP7 TP10 = CMP-0055148-2: Test Point, Multipurpose, Black, TH; Manufacturer: Keystone Electronics; CNHeader: FALSE; ContactFinish: Silver; Green_REACh: Passed; Green_Lifecycle: Active; CT: TRUE
TP8 TP9 TP12 = CMP-0003825-1: 1mm Test Point, SMT; Manufacturer: Any
U7 = CMP-0032881-1: Low-Voltage Adjustable Precision Shunt Regulator, 15 mA, -40 to 85 degC, 5-pin SOT-23 (DBV), Green (RoHS & no Sb/Br); Manufacturer: Texas Instruments; Temp Coeff(Max)(ppm/ degree C): 129; VO Adj(Min)(V): 1.24; SubFamily: Shunt Voltage Reference; Initial Accuracy @ 25/deg C(%): 0.5; Iout/Iz(Max)(mA): 15; VO Adj(Max)(V): 6; Rating: Catalog; Min Iz for Regulation(uA): 80
U8 = CMP-0126544-1: Automotive, 3V to 36V Input, 1V to 7V Output, 2A, Synchronous Buck Converter Power Module, QFN-FCMOD11; Manufacturer: Texas Instruments; SizeZ_mm: 2.1mm; AEC Qualified: Yes; AEC Grade: Grade 1; Nominal Supply Current: 1.2uA; Number Of Outputs: 1; Output Type: Fixed,AdjustableProgrammable; Output Voltage: 5/1-7V; Standoff Height: 0mm; Switching Frequency: 2.2MHz; TaMax_C: +125°C; TaMin_C: -40°C; TJmax_C: +150°C
U9 = CMP-0092532-1: 300-mA, Ultra-Low-Noise, Low-IQ, High PSRR LDO; Manufacturer: Texas Instruments; TJmax_C: +125°C; Min Supply Voltage: 1.6V; SizeZ_mm: 1.45mm; Output Voltage: 3.3V; Number Of Outputs: 1; Nominal Supply Current: 6.5uA; AEC Qualified: No; Accuracy Percentage: 1.5%; Max Supply Voltage: 6V; Dropout Voltage: 145mV; Standoff Height: 0mm; Output Type: Fixed

## Sheet TIDA-010985_CAN.SchDoc
size 431 x 279 mm; DocumentNumber: 4; SheetNumber: 4; SheetTotal: 5; PageSetup: Record=PageOptions¦CenterHorizontal=True¦CenterVertical=True¦PrintScale=1.00¦XCorrection=1.00¦YCorrection=1.00¦PrintKind=0¦BorderSize=5000000¦LeftOffset=0¦BottomOffset=0¦Orientation=2¦PaperLength=1000¦PaperWidth=1000¦Scale=100¦PaperSource=15¦PrintQuality=600¦MediaType=1¦DitherType=10¦PaperKind=Letter¦PrintScaleMode=1
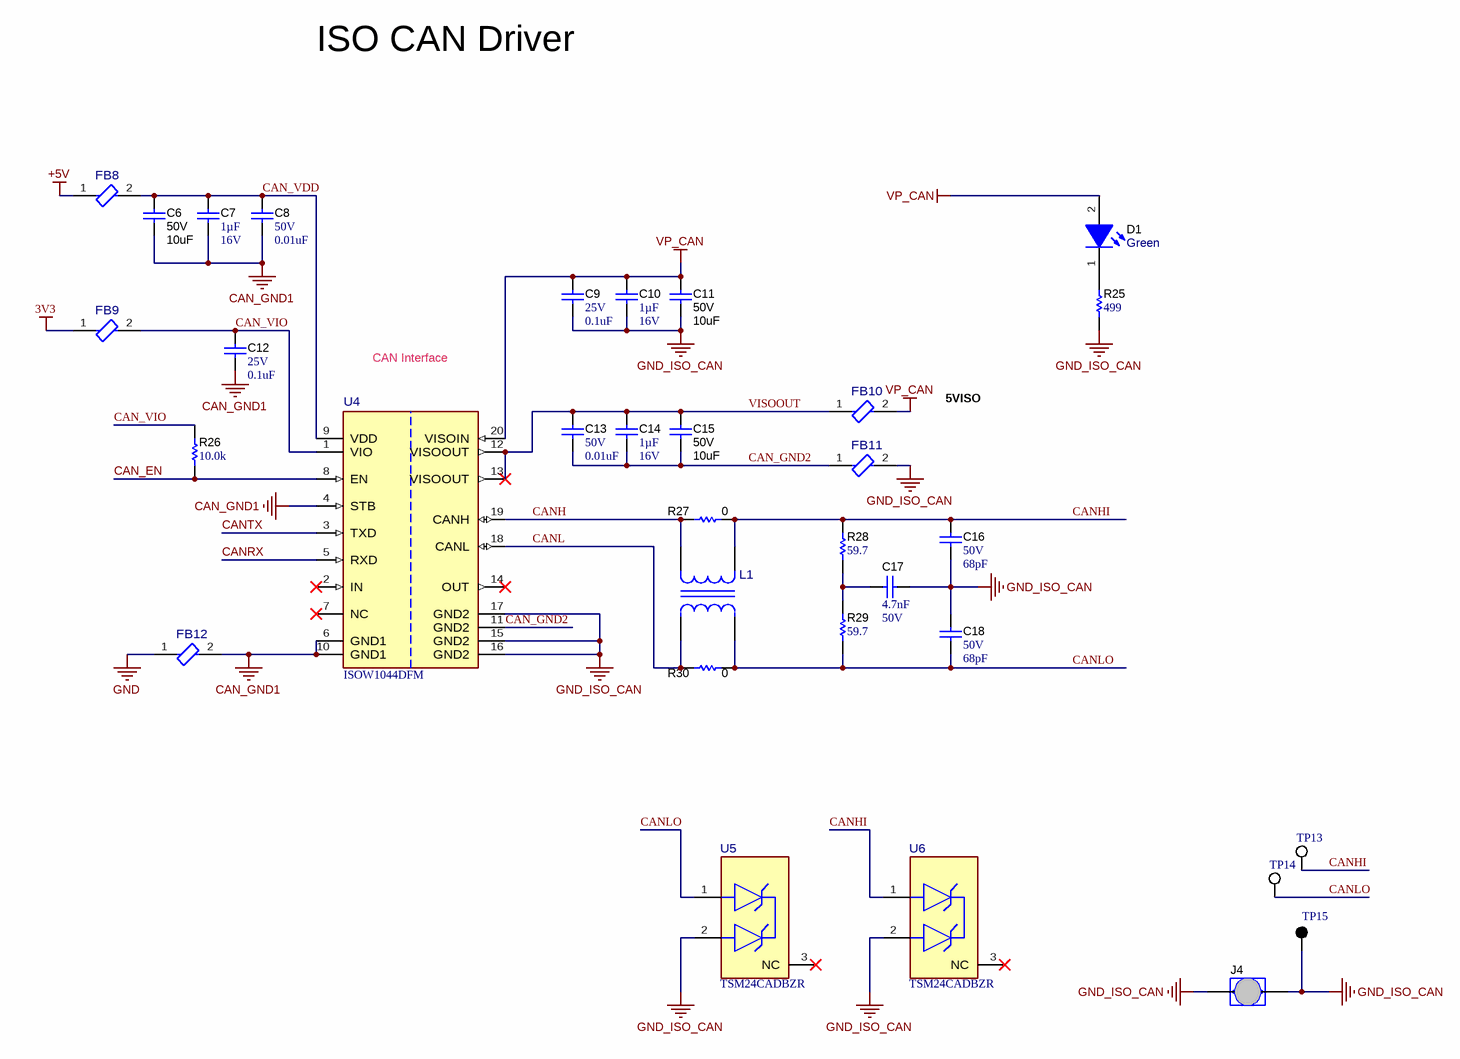
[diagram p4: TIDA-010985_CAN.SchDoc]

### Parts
C6  VDC_V: 50V  ValueDisplayed: 10uF  [1206_180L]  (hidden comment: CL31B106KBHNNNE)
C7  Cap_F: 1µF  VDC_V: 16V  [0603L]  (hidden comment: GCM188R71C105KA64J)
C8  VDC_V: 50V  ValueDisplayed: 0.01uF  [0402L]  (hidden comment: GRM155R71H103KA88D)
C9  VDC_V: 25V  ValueDisplayed: 0.1uF  [0402L]  (hidden comment: GRM155R71E104KE14D)
C10  Cap_F: 1µF  VDC_V: 16V  [0603L]  (hidden comment: GCM188R71C105KA64J)
C11  VDC_V: 50V  ValueDisplayed: 10uF  [1206_180L]  (hidden comment: CL31B106KBHNNNE)
C12  VDC_V: 25V  ValueDisplayed: 0.1uF  [0402L]  (hidden comment: GRM155R71E104KE14D)
C13  VDC_V: 50V  ValueDisplayed: 0.01uF  [0402L]  (hidden comment: GRM155R71H103KA88D)
C14  Cap_F: 1µF  VDC_V: 16V  [0603L]  (hidden comment: GCM188R71C105KA64J)
C15  VDC_V: 50V  ValueDisplayed: 10uF  [1206_180L]  (hidden comment: CL31B106KBHNNNE)
C16  VDC_V: 50V  ValueDisplayed: 68pF  [0402L]  (hidden comment: C1005C0G1H680J050BA)
C17  Cap_F: 4.7nF  VDC_V: 50V  [0603L]  (hidden comment: C0603X472K5RACTU)
C18  VDC_V: 50V  ValueDisplayed: 68pF  [0402L]  (hidden comment: C1005C0G1H680J050BA)
D1  value Green  [WL-SMCW_GREEN]  (hidden comment: 150060VS75000)
FB8  BLM15EX331SN1D  [FP-BLM15EX331SN1D_0402-MFG]  (value not drawn)
FB9  BLM15EX331SN1D  [FP-BLM15EX331SN1D_0402-MFG]  (value not drawn)
FB10  BLM15EX331SN1D  [FP-BLM15EX331SN1D_0402-MFG]  (value not drawn)
FB11  BLM15EX331SN1D  [FP-BLM15EX331SN1D_0402-MFG]  (value not drawn)
FB12  BLM15EX331SN1D  [FP-BLM15EX331SN1D_0402-MFG]  (value not drawn)
J4  999-11-113-10-000000  [Mill-Max_999-11-113-10-000000]  (value not drawn)
L1  ACT45B-101-2P-TL003  [FP-ACT45B-101-2P-TL003_SMT_4MM5_3MM2-MFG]  (value not drawn)
R25  ValueDisplayed: 499  [0603L]  (hidden comment: CRCW0603499RFKEAC)
R26  ValueDisplayed: 10.0k  [0402L]  (hidden comment: CRCW040210K0FKED)
R27  ValueDisplayed: 0  [0603L]  (hidden comment: RCS06030000Z0EA)
R28  ValueDisplayed: 59.7  [0603L]  (hidden comment: RT0603DRE0759R7L)
R29  ValueDisplayed: 59.7  [0603L]  (hidden comment: RT0603DRE0759R7L)
R30  ValueDisplayed: 0  [0603L]  (hidden comment: RCS06030000Z0EA)
TP13  5012  [Keystone5012]  (value not drawn)
TP14  5012  [Keystone5012]  (value not drawn)
TP15  5011  [Keystone5011]  (value not drawn)
U4  ISOW1044DFM  [DFM0020A-MFG]
U5  TSM24CADBZR  [DBZ0003A-MFG]
U6  TSM24CADBZR  [DBZ0003A-MFG]

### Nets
3V3: FB9.1
+5V: FB8.1
CAN_GND1: C6.2 C7.2 C8.2 C12.2 FB12.2 U4.4(STB) U4.6(GND1) U4.10(GND1)
GND: FB12.1
GND_ISO_CAN: C9.2 C10.2 C11.2 C16.2 C17.1 C18.1 FB11.2 J4.1 J4.2 R25.1 TP15.1 U4.15(GND2) U4.16(GND2) U4.17(GND2) U5.2(2_IO) U6.2(2_IO)
VP_CAN: C9.1 C10.1 C11.1 D1.2(A) FB10.2 U4.20(VISOIN)
CAN_EN: R26.1 U4.8(EN)
CAN_GND2: C13.2 C14.2 C15.2 FB11.1 U4.11(GND2)
CAN_VDD: C6.1 C7.1 C8.1 FB8.2 U4.9(VDD)
CAN_VIO: C12.1 FB9.2 R26.2 U4.1(VIO)
CANH: L1.1 R27.2 U4.19(CANH)
CANHI: C16.1 L1.4 R27.1 R28.2 TP13.1 U6.1(1_IO)
CANL: L1.2 R30.2 U4.18(CANL)
CANLO: C18.2 L1.3 R29.1 R30.1 TP14.1 U5.1(1_IO)
CANRX: U4.5(RXD)
CANTX: U4.3(TXD)
VISOOUT: C13.1 C14.1 C15.1 FB10.1 U4.12(VISOOUT) U4.13(VISOOUT)
NetC17_2: C17.2 R28.1 R29.2
NetD1_1: D1.1(K) R25.2

Not connected (* = marked no-connect by the designer): U4 2(IN)* 7(NC)* 14(OUT)*; U5 3(NC)*; U6 3(NC)*

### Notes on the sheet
- ISO CAN Driver
- CAN Interface
- 5VISO

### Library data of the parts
C6 C11 C15 = CMP-0008802-2: as C29 on sheet TIDA-010985_Connectors_Aux_PWR
C7 C10 C14 = CMP-0079154-1: CAP, CERM, 1 µF, 16 V,+/- 10%, X7R, AEC-Q200 Grade 1, 0603; Manufacturer: MuRata; SizeAreaWB_mm2: 4.68; SizeArea_mm2: 1.28; AEC Qualified: Y; AEC Category: Q200; Value: 1uF; TaMax_C: 125°C; SizeZ_mm: 1; Polarized: N; TaMin_C: -55°C; SizeY_mm: 0.8; U/M: EA; SizeX_mm: 1.6; Cap_Case: 0603
C8 C13 = CMP-0006674-2: CAP, CERM, 0.01 uF, 50 V, +/- 10%, X7R, 0402; Manufacturer: MuRata; TaMin_C: -55°C; Polarized: N; SizeAreaWB_mm2: 3; Value1: Unknown; U/M: EA; Value: 0.01uF; TaMax_C: 125°C; SizeZ_mm: 0.6; SizeX_mm: 1; SizeY_mm: 0.5; Cap_Case: 0402; Cap_F: 10nF; AEC Category: Q200
C9 C12 = CMP-0006659-2: CAP, CERM, 0.1 uF, 25 V, +/- 10%, X7R, 0402; Manufacturer: MuRata; TaMin_C: -55°C; Polarized: N; SizeAreaWB_mm2: 3; Value1: Unknown; U/M: EA; Value: 0.1uF; TaMax_C: 125°C; SizeZ_mm: 0.6; SizeX_mm: 1; SizeY_mm: 0.5; Cap_Case: 0402; Cap_F: 100nF; AEC Category: Q200
C16 C18 = CMP-0006251-2: CAP, CERM, 68 pF, 50 V, +/- 5%, C0G/NP0, 0402; Manufacturer: TDK; TaMin_C: -55°C; Polarized: N; SizeAreaWB_mm2: 3; Value1: Unknown; U/M: EA; Value: 68pF; TaMax_C: 125°C; SizeZ_mm: 0.6; SizeX_mm: 1; SizeY_mm: 0.5; Cap_Case: 0402; AEC Category: Q200
C17 = CMP-0006987-4: CAP, CERM, 4700 pF, 50 V, +/- 10%, X7R, 0603; Manufacturer: Kemet; TaMin_C: -55°C; Polarized: N; SizeAreaWB_mm2: 4.68; Value1: Unknown; U/M: EA; Value: 4700pF; TaMax_C: 125°C; SizeZ_mm: 1; SizeX_mm: 1.6; SizeY_mm: 0.8; Cap_Case: 0603; SizeArea_mm2: 1.28; AEC Category: Q200
D1 = CMP-0002894-2: as D3 on sheet TIDA-010985_Connectors_Aux_PWR
FB8-FB12 = CMP-0041881-1: Chip Ferrite Bead, 0402, 330Ω @ 100MHz, 0.205Ω, 25%, 1.1A; Manufacturer: Murata; DCR_ohm: 0.205; SizeZ_mm: 0.55mm; AEC Qualified: No; Ciiva Ids: 2806665; Import Ts: 1521856324
J4 = CMP-0055045-1: as J1 on sheet TIDA-010985_AFE
L1 = CMP-0084086-1: 100µH @ 100kHz 2 Line Common Mode Choke Surface Mount 5.8 kOhms @ 10MHz 150mA DCR 2Ohm; Manufacturer: TDK; AEC Grade: Grade 0; Tolerance_%: +50/-30%; AEC Qualified: Yes; Ind_H: 100uH; SizeZ_mm: 3mm; DCR_ohm: 2Ω; Impedance At Frequency: 5800Ω @ 10MHz; Imax_A: 0.15A
R25 = CMP-0082532-1: as R51 on sheet TIDA-010985_Connectors_Aux_PWR
R26 = CMP-0025958-3: RES, 10.0 k, 1%, 0.063 W, AEC-Q200 Grade 0, 0402; Manufacturer: Vishay-Dale; Power_W: 63mW; TempCo: 100 ppm/C; Value_Code: 10k0; Value: 10.0k; EIA_Code: E96; Res_ohm: 10k; SizeX_mm: 1; SizeY_mm: 0.5; SizeZ_mm: 0.6; Value2: 0.063W; AEC Qualified: Y; VDC_V: 50V; AEC Category: Q200; AEC Grade: 0
R27 R30 = CMP-0081973-1: RES, 0, 0%, 0.25 W, AEC-Q200 Grade 0, 0603; Manufacturer: Vishay-Dale; SizeAreaWB_mm2: 4.68; SizeArea_mm2: 1.28; AEC Qualified: Y; AEC Category: Q200; Value: 0; SizeZ_mm: 1; SizeY_mm: 0.8; Power_W: 250mW; Value2: 0.25W; SizeX_mm: 1.6
R28 R29 = CMP-0025431-3: RES, 59.7, 0.5%, 0.1 W, 0603; Manufacturer: Yageo America; Power_W: 100mW; TempCo: 50 ppm/C; Value_Code: 59R7; U/M: EA; Value: 59.7; EIA_Code: E192; SizeX_mm: 1.6; SizeY_mm: 0.8; SizeZ_mm: 1; Value2: 0.1W; SizeArea_mm2: 1.28; VDC_V: 75V; AEC Category: Q200
TP13 TP14 = CMP-0055149-2: Test Point, Multipurpose, White, TH; Manufacturer: Keystone Electronics; ContactFinish: Silver; CT: TRUE; CNHeader: FALSE; Green_Lifecycle: Active; Green_REACh: Passed
TP15 = CMP-0055148-2: as TP5 on sheet TIDA-010985_Connectors_Aux_PWR
U4 = CMP-0092023-2: Reinforced 5-kVRMS Isolated CAN Transceiver with Integrated lowemissions DC-DC Converter; Manufacturer: Texas Instruments; TJmax_C: +150°C; Max Supply Voltage: 5.5V; AEC Qualified: No; Standoff Height: 0.1mm; Nominal Supply Current: 0.3-124mA; CompType: IC; AEC Category: Q200; TaMax_C: +105°C; SizeZ_mm: 3.55mm; Min Supply Voltage: 1.71V; TaMin_C: -40°C
U5 U6 = CMP-0120116-1: ±24 V Low Capacitance Surge Diode for Industrial Networks in SOT-23 Package; Manufacturer: Texas Instruments; SizeZ_mm: 1.12mm; AEC Qualified: No; Breakdown Voltage: 25.5V; Cap_F: 14pF; Clamping Voltage: 35V; Direction: Bidirectional; Ipp: 30A; Number Of Channels: 1; Ppk: 1200W; Standoff Height: 0.01mm; TaMax_C: +125°C; TaMin_C: -40°C; VRWM: 24V

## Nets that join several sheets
3V3: TIDA-010985_AFE (FB7.1), TIDA-010985_Connectors_Aux_PWR (J5.1 R46.2), TIDA-010985_CAN (FB9.1)
+5V: TIDA-010985_AFE (FB1.1 FB2.1), TIDA-010985_Connectors_Aux_PWR (J5.21 R40.1 R52.2), TIDA-010985_CAN (FB8.1)
GND: TIDA-010985_AFE (22 pins), TIDA-010985_Connectors_Aux_PWR (25 pins), TIDA-010985_CAN (FB12.1)
VDC+: TIDA-010985_AFE (R12.2 R24.2 RN2.4), TIDA-010985_Connectors_Aux_PWR (5 pins)
VDC-: TIDA-010985_AFE (R1.1 R13.1 RN1.4), TIDA-010985_Connectors_Aux_PWR (5 pins)
CAN_EN: TIDA-010985_Connectors_Aux_PWR (R37.1), TIDA-010985_CAN (R26.1 U4.8)
CANRX: TIDA-010985_Connectors_Aux_PWR (R39.1), TIDA-010985_CAN (U4.5)
CANTX: TIDA-010985_Connectors_Aux_PWR (R38.1), TIDA-010985_CAN (U4.3)
SW_EN1: TIDA-010985_AFE (C3.1 U1.3), TIDA-010985_Connectors_Aux_PWR (R35.1)
SW_EN2: TIDA-010985_AFE (C4.1 U2.3), TIDA-010985_Connectors_Aux_PWR (R36.1)
VSENSE_NEG: TIDA-010985_AFE (RN1.5 U3.1), TIDA-010985_Connectors_Aux_PWR (R34.1)
VSENSE_POS: TIDA-010985_AFE (U3.6 U3.7), TIDA-010985_Connectors_Aux_PWR (R33.1)

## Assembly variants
001: not fitted FID1 FID2 FID3 R46 R50 R52 R61 R62 R65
